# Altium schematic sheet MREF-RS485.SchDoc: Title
size A4; CompanyName: TRINAMIC; DocumentNumber: 4; SheetNumber: 4; SheetTotal: 5; Author: Indrek Rebane; DrawnBy: Indrek Rebane; Engineer: Indrek Rebane; Organization: Hedgehog OÜ; Address1: Waterloohain 5; Address2: 22769 Hamburg; Address3: Germany; Address4: tmc_info@trinamic.com
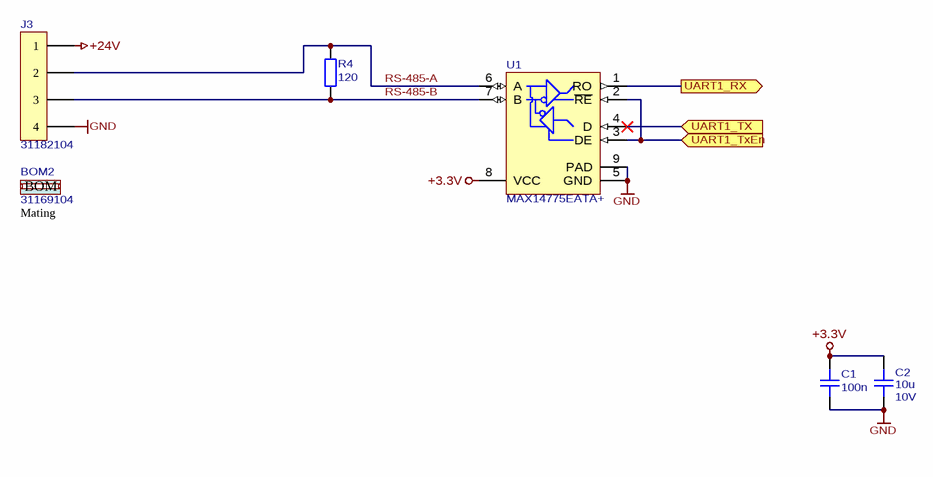
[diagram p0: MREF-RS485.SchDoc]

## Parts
BOM2  Part Number: 31169104  (hidden comment: BOM-ITEM)  (mechanical)
C1  value 100n  [CAPC1005N]  (hidden comment: CAPC)
C2  value 10u  Voltage: 10V  [CAPC2012N]  (hidden comment: CAPC)
J3  Part Number: 31182104  [PT11304HBBN]  (hidden comment: HDR1x4A)
R4  value 120  [RESC1608N]  (hidden comment: RESC)
U1  Part Number: MAX14775EATA+  [SON65P300X80_HS-9N]  (hidden comment: RS485-9)

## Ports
UART1_RX (out), UART1_TX (in), UART1_TxEn (in)

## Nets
+3.3V: C1.2 C2.2 U1.8(VCC)
+24V: J3.1
GND: C1.1 C2.1 J3.4 U1.5(GND) U1.9(PAD)
RS-485-A: J3.2 R4.2 U1.6(A)
RS-485-B: J3.3 R4.1 U1.7(B)
UART1_RX: U1.1(RO) ; port UART1_RX
UART1_TX: U1.4(D) ; port UART1_TX
UART1_TxEn: U1.2(~{RE}) U1.3(DE) ; port UART1_TxEn

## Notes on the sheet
- (near BOM2) Mating

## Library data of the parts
BOM2 = 51639: BOM item; Manufacturer: Metz Connect; Id: 51639; Value: 4 pin, 3.5mm
C1 = 20203: Ceramic chip capacitor; Manufacturer: Any; Part Number: 100n, 50V, X7R, 0402 (1005 metric) chip capacitor; Id: 20203; Voltage: 50V
C2 = 20166: Ceramic chip capacitor; Manufacturer: Any; Part Number: 10u, 10V, X7R, 0805 (2012 metric) chip capacitor; Id: 20166
J3 = 50511: 1X4 pin connector; Manufacturer: Metz Connect; Id: 50511; Value: 4 pin, 3.5mm
R4 = 10047: Chip Resistor; Manufacturer: Any; Part Number: 120, 1%, 100mW, 0603 (1608 metric) chip resistor; Id: 10047; Power: 100mW; Tolerance: 1%
U1 = 51480: Half-duplex RS-485/RS-422 Transceiver; Manufacturer: Maxim Integrated; Id: 51480; Value: RS-485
